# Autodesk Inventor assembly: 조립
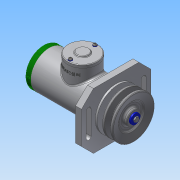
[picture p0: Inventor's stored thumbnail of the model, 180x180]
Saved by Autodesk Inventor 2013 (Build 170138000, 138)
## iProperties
Created: 2017-10
Part Number: 조립
Document SubType Name: Assembly
Designer: Administrator
Author: Administrator
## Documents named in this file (20)
- C:\Users\Administrator\Desktop\471008V1020\조립.iam
- C:\Users\Administrator\Desktop\471008V1020\본체.ipt
- C:\Users\Administrator\Desktop\471008V1020\축.ipt
- C:\Users\Administrator\Desktop\471008V1020\부시1.ipt
- C:\Users\Administrator\Desktop\471008V1020\베어링 15 x 35 x 11.ipt
- C:\Users\Administrator\Desktop\471008V1020\멈춤링 35x1.6.ipt
- C:\Users\Administrator\Desktop\471008V1020\부시2.ipt
- C:\Users\Administrator\Desktop\471008V1020\와셔 10x21.ipt
- C:\Users\Administrator\Desktop\471008V1020\너트 M10.ipt
- C:\Users\Administrator\Desktop\471008V1020\사이드 커버.ipt
- 사이드 커버.ipt
- C:\Users\Administrator\Desktop\471008V1020\멈춤링 15 x 1.ipt
- C:\Users\Administrator\Desktop\471008V1020\오일 실 15 25 7.ipt
- C:\Users\Administrator\Desktop\471008V1020\V-벨트풀리.ipt
- C:\Users\Administrator\Desktop\471008V1020\볼트 M4 x 10.ipt
- C:\Users\Administrator\Desktop\471008V1020\와셔 4x16.ipt
- C:\Users\Administrator\Desktop\471008V1020\키 4 x 4 x 18.ipt
- C:\Users\Administrator\Desktop\471008V1020\탑 커버.ipt
- C:\Users\Administrator\Desktop\471008V1020\십자볼트 M3 x 10.ipt
- C:\Users\Administrator\Desktop\471008V1020\와셔 3x6.ipt
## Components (2 placed, 2 different names)
1. V-벨트풀리:1
2. ISO 4017 M4 x 10:1
